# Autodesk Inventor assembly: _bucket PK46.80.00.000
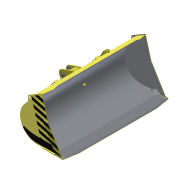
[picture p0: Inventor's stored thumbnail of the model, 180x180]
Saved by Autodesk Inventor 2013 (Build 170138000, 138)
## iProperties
Shininess: 64.0
Length Units: 11269
Angle Units: 11279
Time Units: 11290
Mass Units: 11283
Length Display Precision: 3
Angle Display Precision: 2
Compacted: True
Created: 2005-01
Part Number: _bucket PK46.80.00.000
Document SubType Name: Assembly
Designer: SAlex
Manufacturer: Standard
Standards Organization: Custom
Density: 0.0
Volumn: 0.0
Area: 0.0
PropertySet Name: Model Information
Control State: 0
Master: False
Checked Out: False
Checked Out Date: 2008-10-15
Last Check In Date: 2008-10-15
Author: SAlex
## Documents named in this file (28)
- D:\Vault Workspace\Frontloader\Data\Assy, Chassis, Front\_bucket PK46.80.00.000.iam
- D:\Vault Workspace\Frontloader\Data\Assy, Chassis, Front\PK46.80.00.001.ipt
- D:\Vault Workspace\Frontloader\Data\Assy, Chassis, Front\PK46.80.00.010.iam
- D:\Vault Workspace\Frontloader\Data\Assy, Chassis, Front\PK46.80.00.030.iam
- D:\Vault Workspace\Frontloader\Data\Assy, Chassis, Front\PK46.80.00.021.ipt
- D:\Vault Workspace\Frontloader\Data\Assy, Chassis, Front\PK46.80.00.007.ipt
- D:\Vault Workspace\Frontloader\Data\Assy, Chassis, Front\PK46.80.00.005.ipt
- D:\Vault Workspace\Frontloader\Data\Assy, Chassis, Front\PK46.80.00.008.ipt
- D:\Vault Workspace\Frontloader\Data\Assy, Chassis, Front\PK46.80.00.009.ipt
- D:\Vault Workspace\Frontloader\Data\Assy, Chassis, Front\PK46.80.00.003.ipt
- D:\Vault Workspace\Frontloader\Data\Assy, Chassis, Front\PK46.80.00.004.ipt
- D:\Vault Workspace\Frontloader\Data\Assy, Chassis, Front\PK46.80.00.002.ipt
- D:\Vault Workspace\Frontloader\Data\Assy, Chassis, Front\PK46.80.00.006.ipt
- D:\Vault Workspace\Frontloader\Data\Assy, Chassis, Front\PK46.80.00.025.ipt
- D:\Vault Workspace\Frontloader\Data\Assy, Chassis, Front\PK46.80.00.026.ipt
- D:\Vault Workspace\Frontloader\Data\Assy, Chassis, Front\PK46.80.00.050.iam
- D:\Vault Workspace\Frontloader\Data\Assy, Chassis, Front\PK46.80.00.031-1.ipt
- D:\Vault Workspace\Frontloader\Data\Assy, Chassis, Front\PK46.80.00.030_MIR1.iam
- D:\Vault Workspace\Frontloader\Data\Assy, Chassis, Front\Stripes on Bucket.ipt
- D:\Vault Workspace\Frontloader\Data\Assy, Chassis, Front\Bands to bucket.ipt
- D:\Vault Workspace\Frontloader\Data\Assy, Chassis, Front\Bucket Focus.ipt
- D:\Vault Workspace\Frontloader\Data\Assy, Chassis, Front\PK46.25.00.005.ipt
- D:\Vault Workspace\Frontloader\Data\Assy, Chassis, Front\PK46.25.00.010.iam
- D:\Vault Workspace\Frontloader\Data\Assy, Chassis, Front\PK46.25.00.008.ipt
- D:\Vault Workspace\Frontloader\Data\Assy, Chassis, Front\PK46.25.00.007.ipt
- D:\Vault Workspace\Frontloader\Data\Assy, Chassis, Front\PK46.25.00.020.iam
- Stripes on Bucket.ipt
- Bucket Focus.ipt
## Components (40 placed, 25 different names)
1. PK46.80.00.001:1 — Mate:2, Flush:2, Flush:3, Mate:6, Mate:7, Mate:8, Mate:10, Mate:16, Mate:17, Mate:19, Mate:44, Mate:45, Mate:46, Mate:32, Flush:26, Flush:27, Angle:2, Mate:50, Tangent:1, Mate:52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
2. Bucket Focus:1
3. PK46.80.00.010:1 [sub-assembly] — Mate:7, Flush:6, Flush:7, Mate:25, Flush:18, Mate:42, Mate:43, Tangent:1, Mate:55, Flush:35, Flush:36, Flush:37
4. PK46.80.00.030:1 [sub-assembly] — Mate:2, Mate:18, Mate:33, Mate:36, Mate:63, Mate:64, Mate:69, Mate:80
5. PK46.80.00.021:1 — Flush:2, Flush:3, Mate:6, Mate:9, Mate:11, Flush:14, Mate:20, Flush:15, Mate:67
6. PK46.80.00.007:1 — Mate:8, Flush:6, Mate:9, Mate:12, Mate:13, Angle, Mate:21, Flush:16
7. PK46.80.00.007:2 — Mate:10, Mate:11, Flush:7, Mate:14, Mate:15, Mate:22
8. PK46.80.00.005:1 — Mate:12, Flush:8, Flush:9, Flush:12, Flush:13, Mate:16, Angle, Mate:23
9. PK46.80.00.005:2 — Mate:13, Flush:8, Flush:9
10. PK46.80.00.005:3 — Mate:14, Flush:10, Flush:11, Flush:12, Flush:13, Mate:24
11. PK46.80.00.005:4 — Mate:15, Flush:10, Flush:11
12. PK46.80.00.008:1 — Mate:17, Flush:14, Mate:18
13. PK46.80.00.008:2 — Mate:19, Mate:20, Flush:15
14. PK46.80.00.009:1 — Mate:21, Mate:23, Flush:16, Flush:17
15. PK46.80.00.009:2 — Mate:22, Flush:17, Mate:24
16. PK46.80.00.003:1 — Mate:25, Flush:18, Mate:52, Mate:54
17. PK46.80.00.002:1 — Mate:33, Mate:32, Angle:2, Mate:50, Mate:57, Mate:66, Mate:68
18. PK46.80.00.006:1 — Flush:22, Flush:23
19. PK46.80.00.006:2 — Flush:22, Flush:23, Mate:36
20. PK46.80.00.004:1 — Mate:43, Mate:44, Flush:25
21. PK46.80.00.004:2 — Mate:42, Mate:45, Flush:25, Mate:46
22. PK46.80.00.025:1 — Mate:54, Mate:55, Mate:56, Insert:1
23. PK46.80.00.026:1 — Mate:57, Mate:58, Mate:59
24. PK46.25.00.007:2
25. PK46.25.00.008:2
26. PK46.25.00.020:1 [sub-assembly] — Mate:70
27. PK46.25.00.008:1
28. PK46.25.00.007:1
29. PK46.25.00.005:1
30. PK46.25.00.010:1 [sub-assembly] — Mate:76
31. PK46.25.00.005:2
32. PK46.25.00.008:3
33. PK46.25.00.007:3
34. PK46.25.00.020:2 [sub-assembly] — Mate:73
35. PK46.80.00.050:1 [sub-assembly] — Insert:1, Mate:58, Mate:59
36. PK46.80.00.031-1:1 — Flush:28
37. PK46.80.00.031-1:2 — Mate:63, Mate:64, Flush:28
38. PK46.80.00.030_MIR1:1 [sub-assembly] — Flush:38
39. Bands to bucket:1 — Flush:30, Flush:31, Flush:32
40. Stripes on Bucket:1 — Mate:69, Flush:31, Flush:32
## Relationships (79: Mate 47, Flush 28, Angle 2, Tangent 1, Insert 1)
- Mate:2: PK46.80.00.001:1 ↔ PK46.80.00.030:1
- Flush:2: PK46.80.00.001:1 ↔ PK46.80.00.021:1
- Flush:3: PK46.80.00.001:1 ↔ PK46.80.00.021:1
- Mate:6: PK46.80.00.001:1 ↔ PK46.80.00.021:1
- Mate:7: PK46.80.00.001:1 ↔ PK46.80.00.010:1
- Mate:8: PK46.80.00.001:1 ↔ PK46.80.00.007:1
- Flush:6: PK46.80.00.010:1 ↔ PK46.80.00.007:1
- Mate:9: PK46.80.00.021:1 ↔ PK46.80.00.007:1
- Mate:10: PK46.80.00.001:1 ↔ PK46.80.00.007:2
- Mate:11: PK46.80.00.021:1 ↔ PK46.80.00.007:2
- Flush:7: PK46.80.00.010:1 ↔ PK46.80.00.007:2
- Mate:12: PK46.80.00.007:1 ↔ PK46.80.00.005:1
- Mate:13: PK46.80.00.007:1 ↔ PK46.80.00.005:2
- Mate:14: PK46.80.00.007:2 ↔ PK46.80.00.005:3
- Mate:15: PK46.80.00.007:2 ↔ PK46.80.00.005:4
- Flush:8: PK46.80.00.005:1 ↔ PK46.80.00.005:2
- Flush:9: PK46.80.00.005:1 ↔ PK46.80.00.005:2
- Flush:10: PK46.80.00.005:3 ↔ PK46.80.00.005:4
- Flush:11: PK46.80.00.005:3 ↔ PK46.80.00.005:4
- Flush:12: PK46.80.00.005:1 ↔ PK46.80.00.005:3
- Flush:13: PK46.80.00.005:1 ↔ PK46.80.00.005:3
- Mate:16: PK46.80.00.001:1 ↔ PK46.80.00.005:1
- Angle: PK46.80.00.007:1 ↔ PK46.80.00.005:1
- Mate:17: PK46.80.00.001:1 ↔ PK46.80.00.008:1
- Flush:14: PK46.80.00.021:1 ↔ PK46.80.00.008:1
- Mate:18: PK46.80.00.030:1 ↔ PK46.80.00.008:1
- Mate:19: PK46.80.00.001:1 ↔ PK46.80.00.008:2
- Mate:20: PK46.80.00.021:1 ↔ PK46.80.00.008:2
- Flush:15: PK46.80.00.021:1 ↔ PK46.80.00.008:2
- Mate:21: PK46.80.00.007:1 ↔ PK46.80.00.009:1
- Mate:22: PK46.80.00.007:2 ↔ PK46.80.00.009:2
- Mate:23: PK46.80.00.005:1 ↔ PK46.80.00.009:1
- Flush:16: PK46.80.00.007:1 ↔ PK46.80.00.009:1
- Flush:17: PK46.80.00.009:1 ↔ PK46.80.00.009:2
- Mate:24: PK46.80.00.005:3 ↔ PK46.80.00.009:2
- Mate:25: PK46.80.00.010:1 ↔ PK46.80.00.003:1
- Flush:18: PK46.80.00.010:1 ↔ PK46.80.00.003:1
- Mate:33: PK46.80.00.030:1 ↔ PK46.80.00.002:1
- Flush:22: PK46.80.00.006:1 ↔ PK46.80.00.006:2
- Flush:23: PK46.80.00.006:1 ↔ PK46.80.00.006:2
- Mate:36: PK46.80.00.030:1 ↔ PK46.80.00.006:2
- Mate:42: PK46.80.00.010:1 ↔ PK46.80.00.004:2
- Mate:43: PK46.80.00.010:1 ↔ PK46.80.00.004:1
- Mate:44: PK46.80.00.001:1 ↔ PK46.80.00.004:1
- Mate:45: PK46.80.00.001:1 ↔ PK46.80.00.004:2
- Flush:25: PK46.80.00.004:1 ↔ PK46.80.00.004:2
- Mate:46: PK46.80.00.001:1 ↔ PK46.80.00.004:2
- Mate:32: PK46.80.00.001:1 ↔ PK46.80.00.002:1
- Flush:26: PK46.80.00.001:1
- Flush:27: PK46.80.00.001:1
- Angle:2: PK46.80.00.001:1 ↔ PK46.80.00.002:1
- Mate:50: PK46.80.00.001:1 ↔ PK46.80.00.002:1
- Tangent:1: PK46.80.00.001:1 ↔ PK46.80.00.010:1
- Mate:52: PK46.80.00.001:1 ↔ PK46.80.00.003:1
- Mate:54: PK46.80.00.003:1 ↔ PK46.80.00.025:1
- Mate:55: PK46.80.00.010:1 ↔ PK46.80.00.025:1
- Mate:56: PK46.80.00.001:1 ↔ PK46.80.00.025:1
- Insert:1: PK46.80.00.025:1 ↔ PK46.80.00.050:1
- Mate:57: PK46.80.00.002:1 ↔ PK46.80.00.026:1
- Mate:58: PK46.80.00.026:1 ↔ PK46.80.00.050:1
- Mate:59: PK46.80.00.026:1 ↔ PK46.80.00.050:1
- Mate:63: PK46.80.00.030:1 ↔ PK46.80.00.031-1:2
- Mate:64: PK46.80.00.030:1 ↔ PK46.80.00.031-1:2
- Flush:28: PK46.80.00.031-1:1 ↔ PK46.80.00.031-1:2
- Mate:66: PK46.80.00.002:1
- Mate:67: PK46.80.00.021:1
- Mate:68: PK46.80.00.002:1
- Flush:30: Bands to bucket:1
- Mate:69: PK46.80.00.030:1 ↔ Stripes on Bucket:1
- Flush:31: Bands to bucket:1 ↔ Stripes on Bucket:1
- Flush:32: Bands to bucket:1 ↔ Stripes on Bucket:1
- Flush:35: PK46.80.00.010:1
- Mate:70: PK46.25.00.020:1
- Flush:36: PK46.80.00.010:1
- Mate:73: PK46.25.00.020:2
- Flush:37: PK46.80.00.010:1
- Mate:76: PK46.25.00.010:1
- Flush:38: PK46.80.00.030_MIR1:1
- Mate:80: PK46.80.00.030:1
## Named parameters: d328_d326 = 0
